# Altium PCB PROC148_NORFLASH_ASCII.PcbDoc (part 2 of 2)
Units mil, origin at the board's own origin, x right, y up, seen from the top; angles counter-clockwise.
Board outline 790 x 790 mil, 6 copper layers (Top Layer, GND1, Signal Layer 1, Signal Layer 2, PWR/GND2, Bottom Layer), stack 65.134 mil thick; 36 components, 63 nets, 233 pads, 102 vias.
Unrouted connection lines stored in the file: 1.
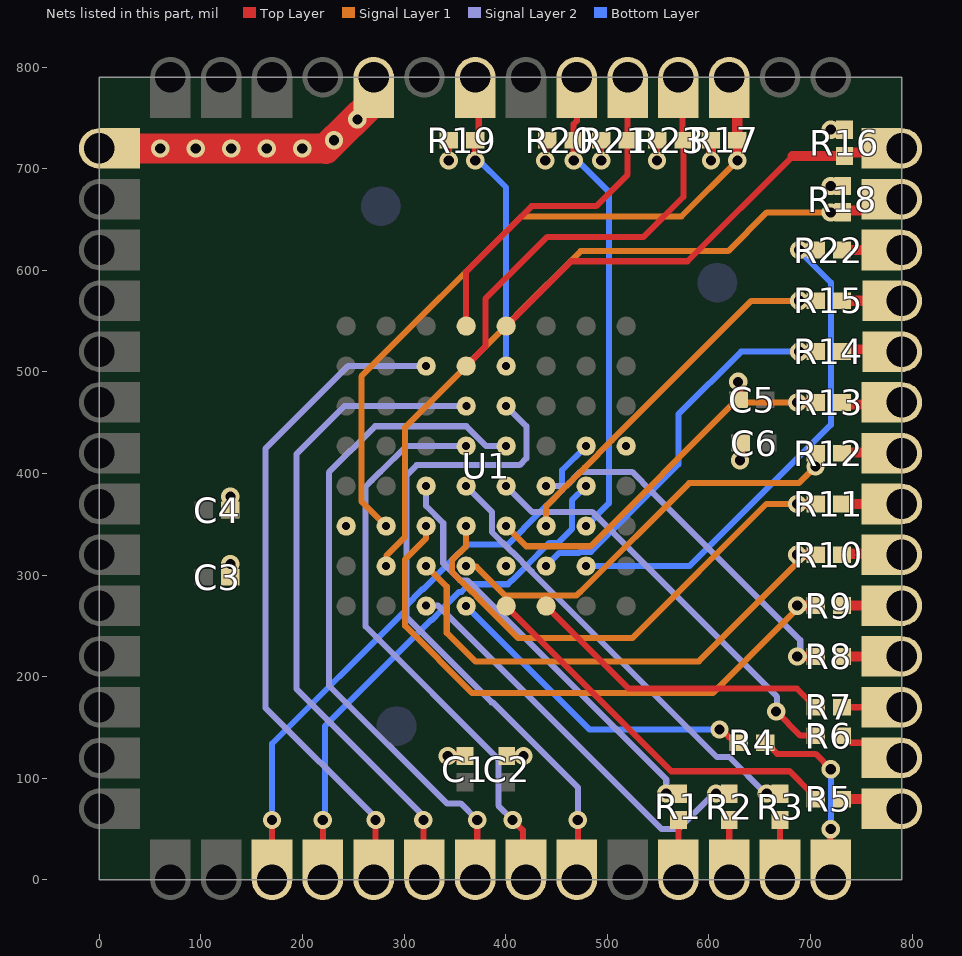
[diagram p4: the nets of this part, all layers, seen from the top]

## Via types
v1: diameter 18, hole 10, Top Layer to Bottom Layer, tented both sides, 65 vias
v2: diameter 14, hole 7.87, Top Layer to Bottom Layer, tented both sides, 37 vias

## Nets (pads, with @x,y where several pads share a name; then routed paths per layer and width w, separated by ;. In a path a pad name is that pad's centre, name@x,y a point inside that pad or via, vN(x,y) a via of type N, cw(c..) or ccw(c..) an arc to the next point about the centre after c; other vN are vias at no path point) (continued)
GPMC0_A15_MUX: pad.3@170,0 pad.4@170,20 U1.D7 | length 558.8
  Top Layer w6: pad.4@170,20 v1(170,59)
  Bottom Layer w6: v1(170,59) 170,134.08 301,265.08 301,269.06 318.02,286.07 318.72,286.07 347.11,314.46 347.11,314.69 355.31,322.89 355.54,322.89 362.65,330 402.02,330 417.72,345.7 417.72,345.93 440.53,368.74 440.76,368.74 455.44,383.42 455.44,403.22 v2(479.22,427)
GPMC0_A16_MUX: pad.3@220,0 pad.4@220,20 U1.E7 | length 504.5
  Top Layer w6: pad.4@220,20 v1(220,59)
  Bottom Layer w6: v1(220,59) 222.13,61.13 222.13,151.47 257.34,186.67 326.66,256 327.54,256 335.74,264.2 335.74,265.08 354.18,283.52 356.52,283.52 364,291 402.11,291 406,294.89 406.28,294.89 420.17,308.78 420.17,309 442.97,331.81 451.66,331.81 465.22,345.37 465.22,373.63 v2(479.22,387.63)
GPMC0_A17_MUX: pad.3@270,0 pad.4@270,20 U1.B3 | length 631.4
  Top Layer w6: pad.4@272,27.96 v1(272,59)
  Signal Layer 2 w6: v1@272,61 163.53,169.47 163.53,424.53 244.74,505.74 v2(321.74,505.74)
GPMC0_A18_MUX: pad.3@320,0 pad.4@320,20 U1.C4 | length 633.9
  Top Layer w6: pad.4@319,20 v1(319,59)
  Signal Layer 2 w6: v1@319,63 194,188 194,419 241.52,466.52 v2(361.44,466.52)
GPMC0_A19_MUX: pad.3@370,0 pad.4@370,20 U1.D5 | length 643
  Top Layer w6: pad.4@372,27.96 v1(372,59)
  Signal Layer 2 w6: v1(372,59) 355.66,75.34 342.04,75.34 226,191.38 226,401.08 271.44,446.51 361.39,446.51 380.91,427 v2(400.48,427)
GPMC0_A20_MUX: pad.3@420,0 pad.4@420,20 U1.D4 | length 546.9
  Top Layer w6: v1(406.85,59) 417,48.85 pad.4@417,20
  Signal Layer 2 w6: v2(361.11,427) 302.17,427 276.8,401.63 276.57,401.63 268.37,393.43 268.37,393.2 262,386.83 262,249.49 392.75,118.74 392.75,73.1 v1(406.85,59)
GPMC0_A21_MUX: pad.3@470,0 pad.4@470,20 U1.C5 | length 633.3
  Top Layer w6: pad.4@471,20 v1(471,59)
  Signal Layer 2 w6: v2(400.48,466.37) 420.34,446.51 420.34,414.86 413.7,408.22 312.34,408.22 302.48,398.36 302.48,258.48 386.16,174.8 387.32,174.8 471,91.13 v1(471,59)
GPMC0_AD0_MUX: pad.3@570,0 pad.4@570,20 R1.2 | length 39
  Top Layer w6: pad.4@570,20 R1.2@570,59.01
GPMC0_AD1_MUX: pad.3@620,0 pad.4@620,20 R2.2 | length 39
  Top Layer w6: pad.4@620,20 R2.2@620,59.01
GPMC0_AD2_MUX: pad.3@670,0 pad.4@670,20 R3.2 | length 59
  Top Layer w6: pad.3@670,0 R3.2@670,59.01
GPMC0_AD3_MUX: pad.3@720,0 pad.4@720,20 R4.2 | length 164.5
  Top Layer w6: R4.2@655.47,135.01 656.25,135.01 667.26,124 705,124 v1(720,109) ; pad.4@719.45,20 719.45,49.45 v1(720,50)
  Bottom Layer w6: v1(720,50) v1(720,109)
GPMC0_AD4_MUX: pad.3@790,70 pad.4@770,70 R5.2 | length 56.6
  Top Layer w6: pad.4@770,66.48 pad.3@790,66.48
  Top Layer w10: R5.2@732.99,79.5 pad.4@769.61,79.5
GPMC0_AD5_MUX: pad.3@790,120 pad.4@770,120.14 R6.2 | length 67.1
  Top Layer w6: R6.2@731.99,142 732.78,142 739.77,135.01 774.99,135.01 pad.3@790,120
GPMC0_AD6_MUX: pad.3@790,170 pad.4@770,170 R7.2 | length 59
  Top Layer w6: R7.2@730.99,170 pad.3@790,170
GPMC0_AD7_MUX: pad.3@790,220 pad.4@770,220 R8.2 | length 59
  Top Layer w10: R8.2@730.99,220 pad.3@790,220
GPMC0_AD8_MUX: pad.3@790,270 pad.4@770,270 R9.2 | length 59
  Top Layer w10: R9.2@730.99,270 pad.3@790,270
GPMC0_AD9_MUX: pad.3@790,320 pad.4@770,320 R10.2 | length 60.8
  Top Layer w10: R10.2@729.99,321 R10.2@730.99,320 731.99,321 pad.3@790,321
GPMC0_AD10_MUX: pad.3@790,370 pad.4@770,370 R11.2 | length 59
  Top Layer w10: R11.2@730.99,370 pad.3@790,370
GPMC0_AD11_MUX: pad.3@790,420 pad.4@770,420 R12.2 | length 59.2
  Top Layer w10: R12.2@730.99,420 731.52,420.53 pad.3@790,420.53
GPMC0_AD12_MUX: pad.3@790,470 pad.4@770,470 R13.2 | length 59.8
  Top Layer w10: R13.2@730.99,470 732.99,468 pad.3@790,468
GPMC0_AD13_MUX: pad.3@790,520 pad.4@771,520 R14.2 | length 59.8
  Top Layer w10: R14.2@730.99,520 732.99,522 pad.4@790,522
GPMC0_AD14_MUX: pad.3@790,570 pad.4@771,570 R15.2 | length 59
  Top Layer w10: R15.2@730.99,570 pad.3@790,570
GPMC0_AD15_MUX: pad.3@790,620 pad.4@770,620 R22.2 | length 59
  Top Layer w10: R22.2@730.99,620 pad.3@790,620
GPMC0_CSN0_MUX: pad.3@620,790 pad.4@620,770 R17.1 U1.F2 | length 700.7
  Top Layer w10: pad.3@620,790 627.99,782.01 R17.1@627.99,728 v1(628,708)
  Signal Layer 1 w6: v2(282.37,348.26) 258,372.63 258,495.63 415.37,653 573,653 v1(628,708)
GPMC0_OEN_REN_MUX: pad.3@790,670 pad.4@770,670 R18.1 U1.G2 | length 726.7
  Top Layer w10: v1(720,657.01) R18.1@731.71,657.01 733.7,659 779,659 pad.3@790,670
  Signal Layer 1 w6: v2(282.37,308.89) 282.64,309.16 282.64,319.25 301,337.61 301,445.63 410.52,555.15 410.52,555.65 473.88,619 619,619 657.01,657.01 v1(720,657.01)
GPMC0_WAIT0_MUX: pad.3@520,790 pad.4@519.99,770 R21.1 U1.A4 | length 347.9
  Top Layer w6: U1.A4@361.11,545.11 361.11,598.74 425.59,663.22 489.07,663.22 519.99,694.14 pad.4@519.99,770 pad.3@520,790
GPMC0_WEN_MUX: pad.3@790,720 pad.4@770,720 R16.1 U1.A5 | length 460.3
  Top Layer w6: U1.A5@400.48,545.11 464.35,608.98 578.93,608.98 682.45,712.5
  Top Layer w10: 682.45,712.5 R16.1@733.51,712.5 737.01,716 pad.3@790,716
GPMC0_WPN_MUX: pad.3@570,790 pad.4@570,770 R23.1 U1.B4 | length 428.7
  Top Layer w6: U1.B4@361.11,505.74 380,524.63 380,571.89 441.11,633 535.74,633 574.99,672.26 R23.1@574.99,728 574,728.99 574,770 pad.3@574,790
HSEC_GPIO45: pad.3@470,790 pad.4@470,770 R20.1 U1.F7 | length 466.8
  Top Layer w6: v1@467,712 467,727.73 R20.1@466.73,728 466.73,743.73 470,747 pad.3@470,790
  Bottom Layer w6: v1@467,712 501.63,677.37 501.63,370.67 v2(479.22,348.26)
  other v1: 467,708
HSEC_GPIO46: pad.3@370,790 pad.4@370,770 R19.1 U1.B5 | length 298.3
  Top Layer w6: v1@370,712 R19.1@369.99,728 373.51,731.51 pad.3@373.51,790
  Bottom Layer w6: v1@370,712 400.48,681.52 v2(400.48,505.74)
  other v1: 370,708
NOR_D0: R1.1 U1.E3 | length 416.4
  Top Layer w6: v1(558,85) R1.1@570,84.99
  Signal Layer 2 w6: v2(321.74,387.63) 321.74,368.06 338.53,351.27 338.53,311.68 355.31,294.89 362,294.89 558,98.89 v1(558,85)
NOR_D1: R2.1 U1.H3 | length 403.9
  Top Layer w6: v1(607,85) R2.1@620,84.99
  Signal Layer 2 w6: v2(321.74,270) 333.51,270 553.51,50 570,50 605,85 v1(607,85)
NOR_D2: R3.1 U1.E4 | length 446
  Top Layer w6: v1(657,85) R3.1@670,84.99
  Signal Layer 2 w6: v2(361.11,387.63) 386.48,362.26 386.48,342.46 406.05,322.89 406.28,322.89 425.85,303.32 425.85,303.09 607.93,121.01 620,121.01 656.01,85 v1(657,85)
NOR_D3: R4.1 U1.H4 | length 324.7
  Top Layer w6: v1(610.36,148.01) 612.14,148.01 619.88,140.28 624.21,140.28 R4.1@629.48,135.01
  Bottom Layer w6: v2(361.11,269.52) 482.62,148.01 v1@610.93,148.01
NOR_D4: R5.1 U1.H5 | length 385.7
  Top Layer w6: U1.H5@400.48,269.52 563,107 679.51,107 700.95,85.56 700.95,84.77 706.22,79.5 R5.1@707.01,79.5
NOR_D5: R6.1 U1.E5 | length 415.9
  Top Layer w6: v1(666.2,165.83) 690.03,142 R6.1@705.01,142
  Signal Layer 2 w6: v2(400.48,387.63) 425.85,362.26 485.02,362.26 667.1,180.18 667.1,166.73 v1(666.2,165.83)
NOR_D6: R7.1 U1.H6 | length 306.4
  Top Layer w6: U1.H6@439.85,269.52 521.07,188.3 686.71,188.3 R7.1@705.01,170
NOR_D7: R8.1 U1.E6 | length 357.7
  Top Layer w10: v1@688.47,220 R8.1@705.01,220
  Signal Layer 2 w6: v2(439.85,387.63) 459.42,387.63 473.42,401.63 524.39,401.63 544.92,381.1 689.95,236.07 689.95,221.48 v1@688.47,220
  other v1: 687,220
NOR_D8: R9.1 U1.F3 | length 574.8
  Top Layer w10: v1@688.47,270 R9.1@705.01,270
  Signal Layer 1 w6: v2(321.74,348.26) 321.74,336.26 301,315.52 301,249.98 367.13,183.85 603.8,183.85 688.47,268.52 v1@688.47,270
  other v1: 687,270
NOR_D9: R10.1 U1.G3 | length 496.1
  Top Layer w10: v1@688.47,320 R10.1@705.01,320
  Signal Layer 1 w6: v2(321.74,308.89) 342,288.63 342,243.23 370.17,215.06 590.11,215.06 686.18,311.12 686.18,317.7 v1@688.47,320
  other v1: 687,320
NOR_D10: R11.1 U1.F4 | length 490.6
  Top Layer w10: v1@688.47,370 R11.1@705.01,370
  Signal Layer 1 w6: v2(361,348.26) 361,328.58 347.11,314.69 347.11,303.09 366.68,283.52 366.91,283.52 375.11,275.32 375.11,275.09 412.2,238 524.68,238 656.68,370 v1@688.47,370
  other v1: 687,370
NOR_D11: R12.1 U1.G4 | length 421.7
  Top Layer w10: v1(705,407) R12.1@705.01,420
  Signal Layer 1 w6: v2(361.11,308.89) 361.69,308.32 371.16,308.32 399.71,279.77 469.67,279.77 473.42,283.52 473.65,283.52 580.66,390.53 688.53,390.53 v1(705,407)
NOR_D12: R13.1 U1.F5 | length 371.4
  Top Layer w10: v1(687,470) R13.1@705.01,470
  Signal Layer 1 w6: v2(400.48,348.26) 420.28,328.46 483.6,328.46 625.14,470 v1(687,470)
NOR_D13: R14.1 U1.G6 | length 380.9
  Top Layer w10: v1(689,520) R14.1@705.01,520
  Bottom Layer w6: v2(439.85,308.89) 452.77,321.81 472.34,321.81 473.42,322.89 483.74,322.89 570,409.15 570,458.36 631.64,520 v1@688.47,520
NOR_D14: R15.1 U1.F6 | length 368.7
  Top Layer w10: v1(689,570) R15.1@705.01,570
  Signal Layer 1 w6: v2(439.85,348.26) 439.85,367.83 462.32,390.3 462.32,390.53 477.66,405.87 477.88,405.87 504.59,432.57 504.59,432.8 641.79,570 v1(689,570)
NOR_D15: R22.1 U1.G7 | length 503
  Top Layer w10: v1@686.81,620 R22.1@705.01,620
  Bottom Layer w6: v2(479.22,308.89) 580.89,308.89 720,448 720,588 688,620 v1@686.81,620
  other v1: 689,620
VDD_3V3_SYS: C1.1 C2.1 C3.1 C4.1 C5.1 C6.1 pad.3@0,720 pad.3@270,790 pad.4@19.86,720 pad.4@270,770 R16.2 R17.2 R18.2 R19.2 R20.2 R21.2 R23.2 U1.D8 U1.F1 U1.G5 | length 467.9
  Top Layer w6: C3.1@128.99,298 v1(129,311) ; v1@344.01,712.5 R19.2@344.01,728 ; v1@439,712 439,726.25 R20.2@440.75,728 ; v1@494.01,712.5 R21.2@494.01,728 ; v1@549.01,712.5 R23.2@549.01,728
  Top Layer w10: C4.1@128.99,364 v1(129,377.29) ; v1(343,122) 359.26,122 C1.1@359.63,122.37 ; U1.G5@400.48,306.48 v2(400.48,308.89) ; C2.1@401,121.99 v1(417.5,122) ; v1@602.01,712.5 R17.2@602.01,728 ; v1@629,488 629.24,487.76 629.24,472.78 C5.1@629.48,472.53 ; v1@631,415 631.24,415.24 631.24,429.76 C6.1@631.48,430 ; v1(720,682.99) R18.2@731.71,682.99 ; v1(720,738.48) 730.24,738.48 733.51,741.75 R16.2@733.51,742.49
  Top Layer w30: pad.4@19.86,720 223.07,719.76 pad.4@269.81,766
  other v1: 630.53,413 628.76,490.24 344.01,708 439,708 494.01,708 549.01,708 602.01,708 60,720 94.94,719.96 129.88,719.93 164.83,719.88 199.77,719.84 231,728 254,748.59
  other v2: 243,348.26 518.59,427
pads on no net: FID1.1 FID2.1 FID3.1 U1.A1 U1.A8 U1.B1 U1.B8 U1.C1 U1.C8 U1.D1 U1.E1 U1.F8 U1.G1 U1.G8 U1.H1 U1.H8

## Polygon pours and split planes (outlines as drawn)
GND on Bottom Layer "BOTTOM_LAYER_GND_P005" (solid, pour order 5): 0,790 0,0 790,0 790,790
GND on Top Layer "TOP_LAYER_GND_P002" (solid, pour order 2): 0,790 0,0 790,0 790,790
VDD_3V3_SYS on PWR/GND2 "PWR/GND2_VDD_3V3_SYS_P001" (solid, pour order 1): 0,790 0,0 790,0 790,790
GND on GND1 "GND1_GND_P000" (solid, pour order 0): 0,790 0,0 790,0 790,790
GND on Signal Layer 2 "SIGNAL_LAYER_2_GND_P004" (solid, pour order 4): 0,790 0,0 790,0 790,790
GND on Signal Layer 1 "SIGNAL_LAYER_1_GND_P003" (solid, pour order 3): 24,790 24,0 790,0 790,790

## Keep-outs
Keep-Out Layer:
  text ".Layer_Name" at 577,-858.49 h60

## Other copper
Top Layer:
  text ".Layer_Name" at 577,-858.49 h60
Bottom Layer:
  text ".Layer_Name" at 577,-858.49 h60

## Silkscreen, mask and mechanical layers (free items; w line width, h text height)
Top Overlay:
  text ".Layer_Name" at 577,-858.49 h60
Bottom Overlay:
  text ".Layer_Name" at 577,-858.49 h60
Top Paste:
  text ".Layer_Name" at 577,-858.49 h60
Bottom Paste:
  text ".Layer_Name" at 577,-858.49 h60
Top Solder:
  text ".Layer_Name" at 577,-858.49 h60
  text ".Layer_Name" at 577,-858.49 h60
Bottom Solder:
  text ".Layer_Name" at 577,-858.49 h60
Drill Guide:
  text ".Layer_Name" at 577,-858.49 h60
M1 Board Outline:
  the board outline again, w10
  text ".Layer_Name" at 577,-858.49 h60
M2 Board Dimensions:
  rectangle: 0,-275 125,-150
  rectangle: 125,-400 500,-275
  lines w7: 0,-275 1000,-275 ; 125,-400 125,-150 ; 250,-400 250,-150 ; 500,-400 500,-150 ; 750,-400 750,-150 ; 0,-400 1000,-400 1000,-150 0,-150 0,-400
  text ".Layer_Name" at 577,-858.49 h60
M3 3D STEP Top:
  text ".Layer_Name" at 577,-858.49 h60
M4 3D STEP Bottom:
  text ".Layer_Name" at 577,-858.49 h60
M5 Assembly Top:
  lines w10: -292,-930.17 6308,-930.17 ; -292,-726.83 6310,-726.83 ; -292,-523.5 -292,-1133.5 3713,-1133.5 6310,-1133.5 6310,-523.5 -291.5,-523.5 -291.5,-1133.5 1284,-1133.5 ; 2173,-1133.5 2173,-523.5 ; 3440,-726.83 3440,-523.5 ; 4280,-726.83 4280,-523.5 ; 4902,-1140 4902,-937.17
  text "COMPONENTS MARKED 'DNP' SHOULD NOT BE POPULATED." at 1153.5,-318.5 h60
  text "ASSEMBLY VARIANT:" at 1153,-434 h60
  text ".VariantName" at 2189,-434 h60
  text "PCB VIEWED FROM TOP SIDE" at -228.5,-655.67 h60
  text "BOARD #:" at 2248,-655.67 h60
  text ".PRJ_Number" at 2793.5,-655.67 h60
  text "REV:" at 3638,-655.67 h60
  text ".PCB_Rev" at 3929.5,-655.67 h60
  text "SVN REV:" at 4476,-655.67 h60
  text ".VersionControl_RevNumber" at 4982,-655.67 h60
  text "TID #:" at 2248,-859 h60
  text ".TID" at 2793.5,-859 h60
  text "PLOT NAME =" at -228.5,-1064.34 h60
  text ".plot_File_Name" at 577,-1064.34 h60
  text "GENERATED    :" at 2250,-1064.34 h60
  text ".Print_Date" at 3119.5,-1064.34 h60
  text ".Print_Time" at 3848.5,-1064.34 h60
  text "TEXAS INSTRUMENTS" at 5113,-1064.34 h60
M6 Assembly Bottom:
  lines w10: -292.5,-727.33 6309.5,-727.33 ; -290.5,-930.67 6309.5,-930.67 ; 1115.5,-1140.5 1115.5,-937.67 ; 1737.5,-727.33 1737.5,-524 ; 2577.5,-727.33 2577.5,-524 ; 3844.5,-1134 3844.5,-524 ; 4733.5,-1134 6309,-1134 6309,-524 -292.5,-524 -292.5,-1134 2304.5,-1134 6309.5,-1134 6309.5,-524
  text "COMPONENTS MARKED 'DNP' SHOULD NOT BE POPULATED." at 6102,-318 h60
  text ".VariantName" at 5058,-434 h60
  text "ASSEMBLY VARIANT:" at 6097,-434 h60
  text ".VersionControl_RevNumber" at 1035.5,-656.17 h60
  text "SVN REV:" at 1541.5,-656.17 h60
  text ".PCB_Rev" at 2088,-656.17 h60
  text "REV:" at 2379.5,-656.17 h60
  text ".PRJ_Number" at 3224,-656.17 h60
  text "BOARD #:" at 3769.5,-656.17 h60
  text "PCB VIEWED FROM BOTTOM SIDE" at 6246,-656.17 h60
  text ".TID" at 3224,-859.5 h60
  text "TID #:" at 3769.5,-859.5 h60
  text "TEXAS INSTRUMENTS" at 904.5,-1064.84 h60
  text ".Print_Time" at 2169,-1064.84 h60
  text ".Print_Date" at 2898,-1064.84 h60
  text "GENERATED    :" at 3767.5,-1064.84 h60
  text ".plot_File_Name" at 5440.5,-1064.84 h60
  text "PLOT NAME =" at 6246,-1064.84 h60
M9 Title Sheet:
  lines w10: -491.5,1041.5 -291.5,1041.5 ; -491.5,3416.5 -291.5,3416.5 ; -491.5,5791.5 -291.5,5791.5 ; 2008.5,-1333.5 2008.5,-1133.5 ; 2008.5,7966.5 2008.5,8166.5 ; 4508.5,-1333.5 4508.5,-1133.5 ; 4508.5,7966.5 4508.5,8166.5 ; 6321,-1133.5 6321,-523.5 11303.5,-523.5 ; 7008.5,-1333.5 7008.5,-1133.5 ; 7008.5,7966.5 7008.5,8166.5 ; 9508.5,-1333.5 9508.5,-1133.5 ; 9508.5,7966.5 9508.5,8166.5 ; 11303.5,-1133.5 11303.5,-523.5 ; 11303.5,-823.5 14303.5,-823.5 ; 11303.5,-223.5 14303.5,-223.5 ; 11304.5,370.5 14304.5,370.5 ; 12008.5,-1333.5 12008.5,-1133.5 ; 12008.5,7966.5 12008.5,8166.5 ; 12808.5,-1123.5 12808.5,-523.5 ; 14303.5,-523.5 11303.5,-523.5 ; 14303.5,76.5 11303.5,76.5 ; 14308.5,66.5 14308.5,-1133.5 ; 14308.5,871 11304.5,871 11303.5,871 11303.5,370.5 11303.5,76.5 ; 14308.5,1041.5 14508.5,1041.5 ; 14308.5,3416.5 14508.5,3416.5 ; 14308.5,5791.5 14508.5,5791.5 ; 11303.5,-523.5 11303.5,76.5 ; 14308.5,-1133.5 14308.5,7966.5 -291.5,7966.5 -291.5,-1133.5 14308.5,-1133.5 ; -491.5,-1333.5 -491.5,8166.5 14508.5,8166.5 14508.5,-1333.5 -491.5,-1333.5
  text "1" at 739.84,8036.5 h70
  text "2" at 3235.5,8036.5 h70
  text "3" at 5724.84,8036.5 h70
  text "4" at 8231.51,8036.5 h70
  text "5" at 10730.5,8036.5 h70
  text "6" at 13235.5,8036.5 h70
  text "A" at -416.5,6893.5 h70
  text "A" at 14383.5,6893.5 h70
  text "B" at -416.5,4513.5 h70
  text "B" at 14383.5,4513.5 h70
  text "C" at -416.5,2138.5 h70
  text "C" at 14383.5,2138.5 h70
  text "PROJECT TITLE:" at 11343.5,277.5 h45
  text ".PRJ_Title" at 11393.5,144.17 h70
  text "DESIGNED FOR:" at 11343.5,-23.5 h45
  text ".PRJ_Customer" at 11393.5,-163.5 h70
  text "D" at -416.5,-231.5 h70
  text "D" at 14383.5,-231.5 h70
  text "FILE NAME:" at 11343.5,-323.5 h45
  text ".PCB_File_Name_No_Path" at 11393.5,-443.5 h70
  text "Texas Instruments (TI) and/or its licensors do not warrant the accuracy or completeness of this specification" at 6374,-605.34 h45
  text "ENGINEER:" at 11343.5,-613.5 h45
  text "LAYOUT BY:" at 12848.5,-613.5 h45
  text "or any information contained therein. TI and/or its licensors do not warrant that this design will meet" at 6329.01,-718 h45
  text ".PRJ_Engineer" at 11393.5,-768.49 h70
  text ".PCB_Layout" at 12899,-768.49 h70
  text "the specifications, will be suitable for your application or fit for any particular purpose, or will operate in" at 6329.01,-830.67 h45
  text ".Layer_Name" at 577,-858.49 h60
  text "ALTIUM DESIGNER VERSION:" at 12848.5,-923.5 h45
  text "an implementation. TI and/or its licensors do not warrant that the design is production worthy. You should" at 6329.01,-943.33 h45
  text "completely validate and test your design implementation to confirm the system functionality for your application." at 6374,-1056 h45
  text ".print_Scale" at 11393.5,-1056.83 h70
  text ".Application_BuildNumber" at 12899,-1056.83 h70
  text "1" at 739.84,-1263.5 h70
  text "2" at 3235.5,-1263.5 h70
  text "3" at 5724.84,-1263.5 h70
  text "4" at 8231.51,-1263.5 h70
  text "5" at 10730.5,-1263.5 h70
  text "6" at 13235.5,-1263.5 h70
M10 Fab Notes:
  drawing of 189 lines, arcs and shapes, not listed
  text "DESIGN INFORMATION" at 12382.02,6356.17 h60
  text "MIN. TRACK WIDTH:" at 11737.46,6224.05 h60
  text "8" at 12833.7,6224.05 h60
  text "MIL" at 12988.46,6224.05 h60
  text "7.874" at 12667.32,6102.36 h60
  text "MIN. CLEARANCE:" at 11737.46,6099.92 h60
  text "MIL" at 12988.46,6099.92 h60
  text "MIN. VIA PAD SIZE:" at 11737.46,5975.8 h60
  text "24" at 12803.71,5975.8 h60
  text "MIL" at 12988.46,5975.8 h60
  text "0.05mm (2MIL)" at 12432.46,5845.9 h60
  text "MINIMUM ANNULAR RING" at 11408.23,5837.67 h60
  text "EXTERNAL" at 13140.46,5837.67 h60
  text "PER" at 11608.23,5727.55 h60
  text "IPC-D-275 CLASS 2 LEVEL C" at 11828.23,5727.54 h60
  text "MIL, HOLES" at 13316.46,5627.07 h60
  text "+/-" at 12924,5618.48 h60
  text "+/-" at 13778,5618.48 h60
  text "REGISTRATION TOLERANCES:" at 11408.23,5617.42 h60
  text "METAL" at 12608,5617.42 h60
  text "5" at 13184.2,5617.42 h60
  text "3" at 14017.2,5617.42 h60
  text "MIL" at 14133.46,5617.42 h60
  text "HOLE SIZE TOLERANCE (UNLESS OTHERWISE SPECIFIED):" at 11408.23,5519.1 h60
  text "+/-" at 13778,5516.23 h60
  text "3" at 14017.2,5515.17 h60
  text "MIL" at 14133.46,5515.17 h60
  text "MATERIAL:" at 11333.46,5377.52 h60
  text "FR-4 High Tg" at 12319.9,5249 h60
  text "X" at 12175.46,5241.01 h60
  text "FR-408" at 11754.46,5236.49 h60
  text "OTHER" at 13242.46,5236.49 h60
  text "62 MIL (1.6mm) +/-10%" at 12074.56,5093.46 h60
  text "X" at 11954.46,5091.01 h60
  text "THICKNESS:" at 11408.23,5085.24 h60
  text "OTHER" at 13359.46,5085.24 h60
  text "TOLERANCE:" at 11408.23,4946.92 h60
  text "X" at 12256.46,4946.92 h60
  text "ANSI IPC-6012 TYPE 3 CLASS 2" at 12434.48,4946.92 h60
  text "OTHER +/-" at 12434.46,4802.73 h60
  text "BOW & TWIST:" at 11408.23,4657.54 h60
  text "X" at 12256.46,4657.54 h60
  text "ANSI IPC-6012 TYPE 3 CLASS 2" at 12434.48,4657.54 h60
  text "OTHER +/-" at 12434.46,4510.85 h60
  text "DRILLING:" at 11333.46,4380.23 h60
  text "NC_DRILL FILES" at 13094.46,4275.04 h60
  text "REFERENCE:" at 11408.23,4271.1 h60
  text "X" at 12065.46,4271.01 h60
  text "AS SHOWN" at 12243.46,4271.1 h60
  text "X" at 12966.46,4271.1 h60
  text "OTHER" at 13392.46,4128.85 h60
  text "PTH COPPER THICKNESS:" at 11407.91,4125.32 h60
  text "X" at 12547.14,4125.32 h60
  text "20-30 um" at 12675.14,4125.32 h60
  text "BOARD FINISH:" at 11333.46,3977.73 h60
  text "SILKSCREEN:" at 11488.68,3867.6 h60
  text "X" at 12446.46,3867.6 h60
  text "TOP" at 12563.46,3867.6 h60
  text "X" at 12956.46,3867.6 h60
  text "BOTTOM" at 13074.46,3867.6 h60
  text "SILKSCREEN COLOR:" at 11488.68,3712.41 h60
  text "X" at 12445.46,3712.41 h60
  text "WHITE" at 12563.46,3712.41 h60
  text "OTHER" at 13074.46,3712.41 h60
  text "X" at 12576.46,3568.96 h60
  text "GREEN" at 12694.46,3568.96 h60
  text "OTHER" at 13312.46,3568.96 h60
  text "SOLDER RESIST COLOR:" at 11488.68,3562.1 h60
  text "X" at 12576.46,3414.71 h60
  text "MATTE" at 12694.46,3414.71 h60
  text "SEMI-GLOSS" at 13312,3414.07 h60
  text "IMMERSION GOLD (ENIG)" at 12394.46,3241.94 h60
  text "ENEPIG" at 13732,3234.72 h60
  text "SURFACE FINISH:" at 11333.46,3233.72 h60
  text "X" at 12216.46,3233.72 h60
  text "IMM. TIN/SILVER OR EQUIV" at 11663,3096.4 h60
  text "OTHER" at 13094.46,3092.47 h60
  text "ARRAY/PANEL:" at 11333.46,2937.09 h60
  text "CUT AND TRIM PER M1 BOARD OUTLINE" at 12394.46,2928.87 h60
  text "N.C. ROUTE" at 12394.46,2792.9 h60
  text "X" at 13082.46,2792.9 h60
  text "V. SCORE" at 13260.46,2792.9 h60
  text "CERTIFICATION:" at 11333.46,2663.77 h60
  text "MATERIALS AND WORKMANSHIP FOR ALL PCBS" at 12058.46,2663.77 h60
  text "TO MEET OR EXCEED THE REQUIREMENTS OF:" at 12058.46,2569.71 h60
  text "X" at 11695.97,2441.08 h60
  text "ANSI IPC-A-600F CLASS ->" at 11823.96,2441.08 h60
  text "X" at 13471.97,2441.08 h60
  text "2" at 13581.96,2441.08 h60
  text "1" at 13266.96,2439.58 h60
  text "3" at 13935.96,2439.58 h60
  text "X" at 12507.97,2293.39 h60
  text "RoHS" at 12635.96,2293.39 h60
  text "OTHER" at 13280.36,2293.39 h60
  text "PER ORDER" at 13677.42,2293.39 h60
  text "ALL BOARDS MUST MEET OR EXCEED UL94-V0 REQUIREMENTS." at 11361,2139.57 h60
  text "PCB MUST BEAR THE UL94V-0 UL REGISTERED MATERIAL ID NUMBER" at 11361,2023.5 h60
  text "ADDITIONAL REQUIREMENTS:" at 11333.46,1854.08 h60
  text "MICROSECTION:" at 11408.23,1746.95 h60
  text "YES" at 12313.96,1746.95 h60
  text "REQUIRED" at 13175.46,1602.62 h60
  text "BARE BOARD ELEC. TEST:" at 11408.23,1599.76 h60
  text "NONE" at 12713.96,1599.76 h60
  text "X" at 13057.46,1599.76 h60
  text "PER ORDER" at 13767.46,1599.76 h60
  text "XX MIL VIAS REQUIRE NON-CONDUCTIVE FILL AND PLANARIZE" at 11576.38,1394.82 h59
  text "XX MIL VIAS REQUIRE CONDUCTIVE FILL AND PLANARIZE" at 11584.38,1290.84 h60
  text "OUTER XX MIL TRACES REQUIRE 50 OHM SINGLE-ENDED IMPEDANCE" at 11583.39,1127.46 h58
  text "LAYER 2 & 3 (INNER LAYERS) XX MIL WIDE, XX MIL SPACE / TRACES REQUIRE 100 OHM DIFFERENTIAL IMPEDANCE" at 11575.39,891.74 h60
  text ".Layer_Name" at 577,-858.49 h60
M11 Gerber Information:
  lines w10: -292,-930.17 6308,-930.17 ; -292,-726.83 6310,-726.83 ; -292,-523.5 -292,-1133.5 3713,-1133.5 6310,-1133.5 6310,-523.5 -291.5,-523.5 -291.5,-1133.5 1284,-1133.5 ; 2173,-1133.5 2173,-523.5 ; 3440,-726.83 3440,-523.5 ; 4280,-726.83 4280,-523.5 ; 4902,-1140 4902,-937.17
  text "ALL ARTWORK VIEWED FROM TOP SIDE" at -228.5,-655.67 h60
  text "BOARD #:" at 2248,-655.67 h60
  text ".PRJ_Number" at 2793.5,-655.67 h60
  text "REV:" at 3638,-655.67 h60
  text ".PCB_Rev" at 3929.5,-655.67 h60
  text "SVN REV:" at 4476,-655.67 h60
  text ".VersionControl_RevNumber" at 4982,-655.67 h60
  text "LAYER NAME =" at -228.5,-858.49 h60
  text "TID #:" at 2248,-859 h60
  text ".TID" at 2793.5,-859 h60
  text "PLOT NAME =" at -228.5,-1064.34 h60
  text ".plot_File_Name" at 577,-1064.34 h60
  text "GENERATED    :" at 2250,-1064.34 h60
  text ".Print_Date" at 3119.5,-1064.34 h60
  text ".Print_Time" at 3848.5,-1064.34 h60
  text "TEXAS INSTRUMENTS" at 5113,-1064.34 h60
M12 Stackup:
  drawing of 399 lines, arcs and shapes, not listed
  text "Layer" at 5985.46,7482.01 h60
  text "Name" at 6395.38,7482.01 h60
  text "Material" at 7335.12,7482.01 h60
  text "Thickness" at 8194.88,7482.01 h60
  text "Constant" at 8844.72,7482.01 h60
  text "Board Layer Stack" at 9414.58,7482.01 h60
  text "Top Overlay" at 6395.38,7362.01 h60
  text "Top Solder" at 6395.38,7242.01 h60
  text "Solder Resist" at 7335.12,7242.01 h60
  text "0.40mil" at 8194.88,7242.01 h60
  text "3.5" at 8844.72,7242.01 h60
  text "1" at 5985.46,7122.01 h60
  text "Top Layer" at 6395.38,7122.01 h60
  text "0.69mil" at 8194.88,7122.01 h60
  text "Dielectric 1" at 6395.38,7002.01 h60
  text "FR-4" at 7335.12,7002.01 h60
  text "3.70mil" at 8194.88,7002.01 h60
  text "4.1" at 8844.72,7002.01 h60
  text "2" at 5985.46,6882.01 h60
  text "GND1" at 6395.38,6882.01 h60
  text "0.69mil" at 8194.88,6882.01 h60
  text "Dielectric 3" at 6395.38,6762.01 h60
  text "PP-006" at 7335.12,6762.01 h60
  text "2.80mil" at 8194.88,6762.01 h60
  text "4.1" at 8844.72,6762.01 h60
  text "3" at 5985.46,6642.01 h60
  text "Signal Layer 1" at 6395.38,6642.01 h60
  text "CF-004" at 7335.12,6642.01 h60
  text "0.69mil" at 8194.88,6642.01 h60
  text "Dielectric1" at 6395.38,6522.01 h60
  text "FR-4" at 7335.12,6522.01 h60
  text "48.00mil" at 8194.88,6522.01 h60
  text "4.8" at 8844.72,6522.01 h60
  text "4" at 5985.46,6402.01 h60
  text "Signal Layer 2" at 6395.38,6402.01 h60
  text "CF-004" at 7335.12,6402.01 h60
  text "0.69mil" at 8194.88,6402.01 h60
  text "Dielectric 4" at 6395.38,6282.01 h60
  text "PP-006" at 7335.12,6282.01 h60
  text "2.80mil" at 8194.88,6282.01 h60
  text "4.1" at 8844.72,6282.01 h60
  text "5" at 5985.46,6162.01 h60
  text "PWR/GND2" at 6395.38,6162.01 h60
  text "0.69mil" at 8194.88,6162.01 h60
  text "Dielectric 2" at 6395.38,6042.01 h60
  text "FR-4" at 7335.12,6042.01 h60
  text "3.70mil" at 8194.88,6042.01 h60
  text "4.1" at 8844.72,6042.01 h60
  text "6" at 5985.46,5922.01 h60
  text "Bottom Layer" at 6395.38,5922.01 h60
  text "0.69mil" at 8194.88,5922.01 h60
  text "Bottom Solder" at 6395.38,5802.01 h60
  text "Solder Resist" at 7335.12,5802.01 h60
  text "0.40mil" at 8194.88,5802.01 h60
  text "3.5" at 8844.72,5802.01 h60
  text "Bottom Overlay" at 6395.38,5682.01 h60
  text ".Layer_Name" at 577,-858.49 h60
M13 Component Bodies Top:
  text ".Layer_Name" at 577,-858.49 h60
M14 Component Bodies Bottom:
  text ".Layer_Name" at 577,-858.49 h60
M15 Courtyards Top:
  text ".Layer_Name" at 577,-858.49 h60
M16 Courtyards Bottom:
  text ".Layer_Name" at 577,-858.49 h60
Drill Drawing:
  circle w10: c5363.72,3290.28 r27.63
  lines w10: 5336.09,3014.02 5391.34,3014.02 5391.34,3069.27 5336.09,3069.27 5336.09,3014.02 ; 5336.09,3193.59 5391.34,3193.59 5363.72,3138.34 5336.09,3193.59
  lines w12: 5286,2976.72 8517.49,2976.72 ; 5286,3349.68 8517.49,3349.68 ; 5623.86,2852.4 5623.86,3474 ; 5955.86,2852.4 5955.86,3474 ; 6592.43,2852.4 6592.43,3474 ; 6851.57,2852.4 6851.57,3474 ; 7226.72,2852.4 7226.72,3474 ; 7951.05,2852.4 7951.05,3474 ; 5286,2852.4 8517.49,2852.4 8517.49,3474 5286,3474 5286,2852.4
  text "Symbol" at 5360.59,3386.98 h72
  text "Quantity" at 5661.16,3386.98 h72
  text "Finished Hole Size" at 5993.16,3386.98 h72
  text "Plated" at 6629.72,3386.98 h72
  text "Hole Type" at 6888.86,3386.98 h72
  text "Drill Layer Pair" at 7264.02,3386.98 h72
  text "Hole Tolerance" at 7988.35,3386.98 h72
  text "37" at 5661.16,3262.66 h60
  text "7.87mil (0.200mm)" at 5993.16,3262.66 h60
  text "PTH" at 6629.72,3262.66 h60
  text "Round" at 6888.86,3262.66 h60
  text "Top Layer - Bottom Layer" at 7264.02,3262.66 h60
  text "65" at 5661.16,3138.34 h60
  text "10.00mil (0.254mm)" at 5993.16,3138.34 h60
  text "PTH" at 6629.72,3138.34 h60
  text "Round" at 6888.86,3138.34 h60
  text "Top Layer - Bottom Layer" at 7264.02,3138.34 h60
  text "56" at 5661.16,3014.02 h60
  text "30.00mil (0.762mm)" at 5993.16,3014.02 h60
  text "PTH" at 6629.72,3014.02 h60
  text "Round" at 6888.86,3014.02 h60
  text "Top Layer - Bottom Layer" at 7264.02,3014.02 h60
  text "158 Total" at 5661.16,2889.7 h60
  text ".Layer_Name" at 577,-858.49 h60
M17 Embedded Cavity:
  text ".Layer_Name" at 577,-858.49 h60
M18 Embedded Assembly:
  text ".Layer_Name" at 577,-858.49 h60
M19 Embedded Keepout:
  text ".Layer_Name" at 577,-858.49 h60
